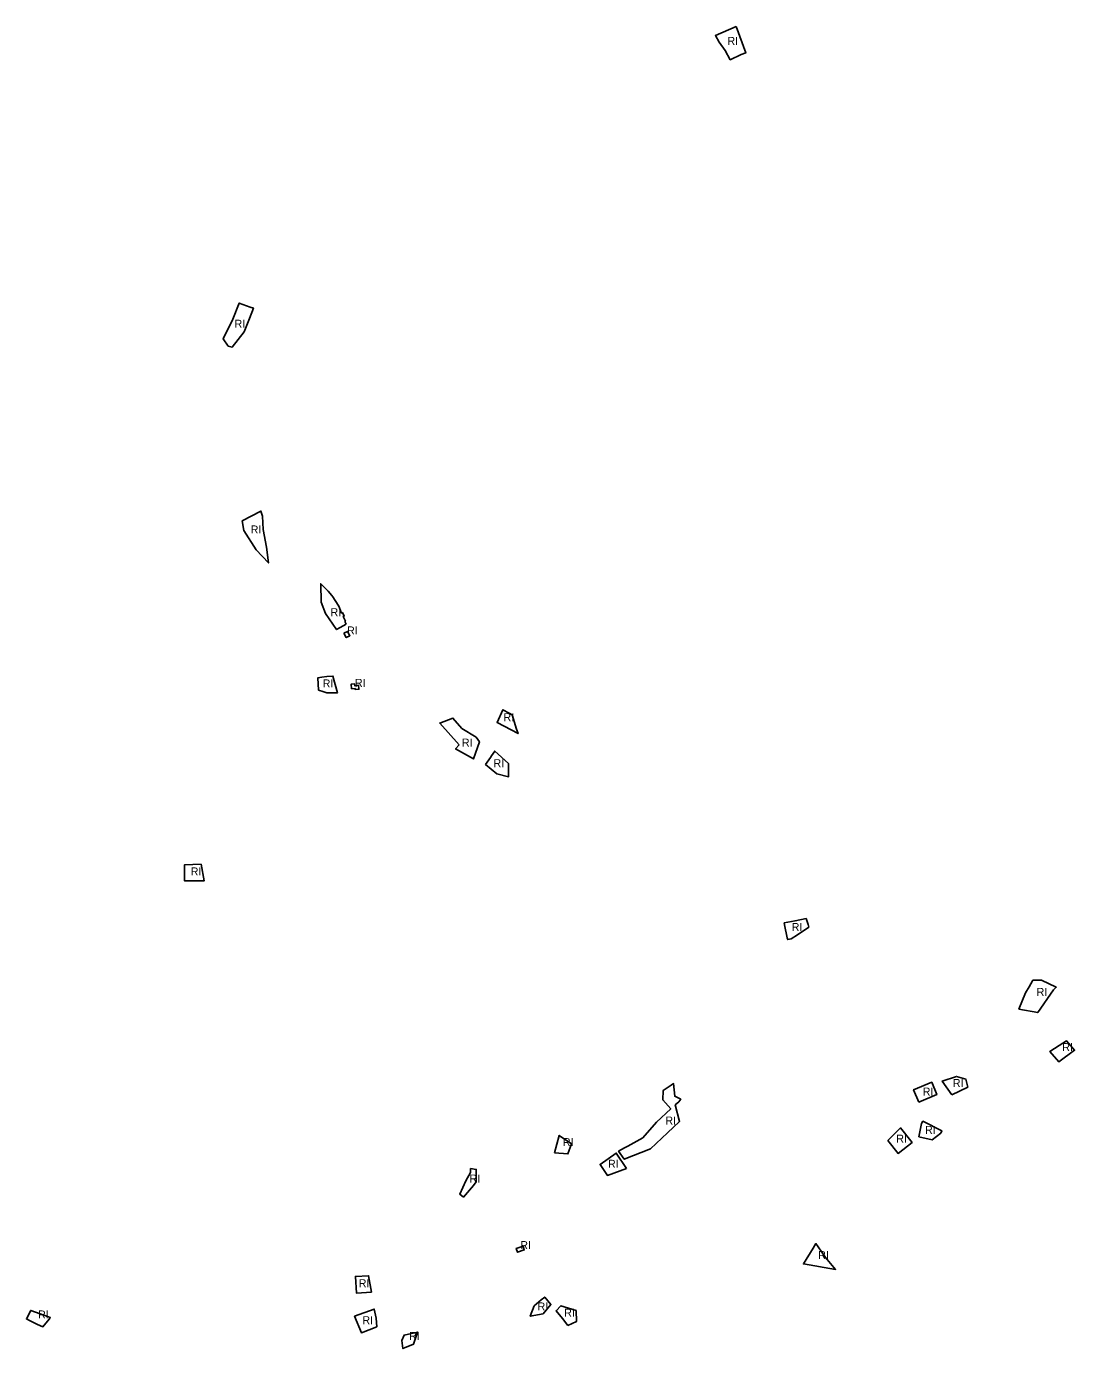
# Model space of a CAD drawing. Extents: x -477010 to -466219, y -1158799 to -1150161.
# Drawn here: x -475672 to -474494, y -1152003 to -1150517 of the extents above; entities that cross this region are included whole.
import ezdxf

# ---------------------------------------------------------------- set-up
doc = ezdxf.new("R2010")
doc.units = 0
doc.layers.add('19', color=7, linetype='Continuous')

msp = doc.modelspace()

# ---------------------------------------------------------------- linework, layer by layer
at = {"layer": '19'}
for points in [[(-474873.894, -1150516.832), (-474863.301, -1150546.649), (-474868.57, -1150548.26), (-474880.57, -1150554.23), (-474886.37, -1150543.98), (-474893.05, -1150534.4), (-474897.25, -1150527.08)], [(-475445.06, -1150876.3), (-475450.48, -1150868.13), (-475439.87, -1150845.88), (-475432.6, -1150827.88), (-475420.15, -1150832.34), (-475416.67, -1150833.57), (-475420.91, -1150845.37), (-475427.03, -1150860.15), (-475440.69, -1150877.53)], [(-475405.79, -1151082.6), (-475401.86, -1151102.21), (-475399.78, -1151119.93), (-475413.48, -1151105.43), (-475427.54, -1151083.39), (-475429.35, -1151072.84), (-475408.21, -1151061.72), (-475406.51, -1151067.57)], [(-475312.45, -1151189.04), (-475319.27, -1151192.74), (-475323.11, -1151194.98), (-475335.56, -1151176.83), (-475340.57, -1151164.28), (-475340.92, -1151143.36), (-475332.66, -1151151.78), (-475328.55, -1151156.71), (-475327.47, -1151158), (-475324.79, -1151162.19), (-475320.66, -1151168.63), (-475317.54, -1151176.31), (-475316.53, -1151175.8), (-475314.56, -1151179.69), (-475315.82, -1151180.35), (-475313.22, -1151185.6), (-475313.76, -1151185.87)], [(-475314.87, -1151199.06), (-475310.79, -1151196.93), (-475308.13, -1151201.83), (-475312.3, -1151204)], [(-475343.57, -1151263.17), (-475344.3, -1151249.25), (-475339.71, -1151248.42), (-475333.99, -1151247.87), (-475327.22, -1151247.21), (-475322.21, -1151266.21), (-475334.26, -1151265.95), (-475338.8, -1151264.47)], [(-475306.33, -1151261.58), (-475306.93, -1151256.5), (-475302.91, -1151256.02), (-475302.67, -1151258.02), (-475298.62, -1151257.54), (-475298.09, -1151262.02), (-475302.14, -1151262.5), (-475302.31, -1151261.1)], [(-475120.79, -1151306.87), (-475119.19, -1151311.96), (-475142.77, -1151299.55), (-475136.14, -1151285), (-475129.18, -1151289.02), (-475125.79, -1151290.97)], [(-475185.53, -1151324.37), (-475207.23, -1151300.13), (-475192.41, -1151294.46), (-475182.36, -1151306.31), (-475166.39, -1151315.96), (-475162.64, -1151321.12), (-475169.4, -1151340.39), (-475189.37, -1151329.11)], [(-475150.33, -1151338.79), (-475149.05, -1151336.97), (-475145.29, -1151331.65), (-475129.88, -1151345.62), (-475129.87, -1151360.49), (-475143, -1151357.08), (-475155.73, -1151346.46)], [(-475475.46, -1151458.57), (-475472.04, -1151477.58), (-475494.06, -1151477.47), (-475493.97, -1151459.27)], [(-474820.15, -1151524.64), (-474807.75, -1151522.27), (-474795.49, -1151519.93), (-474793.17, -1151526.67), (-474792.19, -1151529.53), (-474805.07, -1151538.08), (-474812.03, -1151542.7), (-474816.03, -1151543.57), (-474816.52, -1151541.39), (-474819.7, -1151526.79)], [(-474544.77, -1151596.68), (-474540.81, -1151589.73), (-474540.47, -1151589.13), (-474530.63, -1151589.29), (-474514.13, -1151597.17), (-474517.23, -1151600.13), (-474535.03, -1151625.51), (-474556.17, -1151621.66), (-474548.67, -1151603.54)], [(-474510.96, -1151662.56), (-474502.76, -1151657.29), (-474493.64, -1151667.85), (-474511.44, -1151680.88), (-474521.57, -1151669.37)], [(-474999.35, -1151777.69), (-474995.67, -1151775.64), (-474979.03, -1151766.4), (-474963.73, -1151748.89), (-474947.61, -1151733.81), (-474956.56, -1151723.69), (-474955.98, -1151713.11), (-474947.02, -1151707.13), (-474944.42, -1151705.4), (-474943.01, -1151719.59), (-474936.23, -1151722.95), (-474938.29, -1151725.9), (-474942.49, -1151729.46), (-474937.61, -1151747.93), (-474951.01, -1151760.9), (-474970.24, -1151778.87), (-474999.9, -1151790.39), (-475006.13, -1151781.45)], [(-474668.8, -1151726.16), (-474674.49, -1151712.28), (-474654.13, -1151703.94), (-474648.45, -1151717.82)], [(-474631.6, -1151718.23), (-474642.41, -1151702.61), (-474626.42, -1151697.43), (-474615.92, -1151700.34), (-474613.69, -1151709.31)], [(-474665.52, -1151750.46), (-474664.17, -1151747.78), (-474642.71, -1151758.52), (-474644.05, -1151761.2), (-474653.59, -1151768.64), (-474668.6, -1151765.19)], [(-475078.11, -1151783.14), (-475072.81, -1151763.75), (-475058.98, -1151773.04), (-475063.16, -1151784.4)], [(-474703.47, -1151769.37), (-474689.11, -1151755.28), (-474676.31, -1151771.55), (-474692.03, -1151783.91)], [(-474997.21, -1151800.96), (-475018.68, -1151808.67), (-475027.04, -1151796.22), (-475008.82, -1151783.51)], [(-475169.35, -1151819.86), (-475180.509, -1151832.92), (-475184.757, -1151829.819), (-475177.71, -1151814.9), (-475172.71, -1151805.42), (-475172.626, -1151800.88), (-475166.224, -1151801.918), (-475166.08, -1151816.04)], [(-474782.02, -1151888.76), (-474773.41, -1151900.92), (-474762.29, -1151914.39), (-474798.33, -1151908.22), (-474787.57, -1151890.42), (-474784.42, -1151885.37)], [(-475113.59, -1151888.11), (-475112.18, -1151892.34), (-475119.81, -1151894.96), (-475121.28, -1151890.63)], [(-475284.06, -1151939.79), (-475300.68, -1151941.1), (-475302.06, -1151922.27), (-475287.23, -1151921.42)], [(-475090.89, -1151964.37), (-475105.47, -1151967.01), (-475101.04, -1151955.45), (-475093.37, -1151948.64), (-475089.08, -1151945.48), (-475082.29, -1151953.67)], [(-475668.32, -1151971.79), (-475671.78, -1151969.91), (-475666.92, -1151960.48), (-475647.13, -1151967.66), (-475645.02, -1151968.43), (-475646.18, -1151970.17), (-475653.27, -1151978.88), (-475659.17, -1151976.1)], [(-475277.82, -1151978.86), (-475295.31, -1151985.62), (-475302.91, -1151967), (-475280.74, -1151959.02), (-475278.51, -1151969.18)], [(-475063.174, -1151977.396), (-475069.11, -1151969.41), (-475076.49, -1151960.87), (-475071.07, -1151955.15), (-475053.93, -1151960.53), (-475053.55, -1151973.06)], [(-475249.65, -1151994.37), (-475247.28, -1151988.21), (-475232.17, -1151984.8), (-475236.77, -1151998.47), (-475248.64, -1152003.31)]]:
    msp.add_lwpolyline(points, close=True, dxfattribs=at)

# ---------------------------------------------------------------- texts
for p in [(-474883.832, -1150537.6615), (-475437.8386, -1150855.6218), (-475419.7377, -1151086.915), (-475329.9617, -1151179.9324), (-475311.453, -1151200.458), (-475338.8117, -1151260.0113), (-475302.56, -1151259.369), (-475135.5256, -1151297.989), (-475182.333, -1151326.5203), (-475146.7828, -1151349.7015), (-475487.1538, -1151471.3998), (-474811.6268, -1151533.8574), (-474536.277, -1151606.866), (-474507.434, -1151668.935), (-474630.4574, -1151709.2686), (-474664.3549, -1151718.8824), (-474953.64, -1151751.459), (-475068.758, -1151775.752), (-474694.0575, -1151771.8281), (-474661.7926, -1151761.9425), (-475018.1132, -1151800.117), (-475173.792, -1151816.694), (-475116.666, -1151891.509), (-474781.862, -1151902.707), (-475298.2667, -1151934.391), (-475658.795, -1151969.51), (-475097.2228, -1151960.4937), (-475067.3748, -1151967.5158), (-475294.1807, -1151975.8948), (-475241.786, -1151993.55)]:
    msp.add_text('RI', height=9, dxfattribs=at).set_placement(p)

doc.saveas('drawing.dxf')
